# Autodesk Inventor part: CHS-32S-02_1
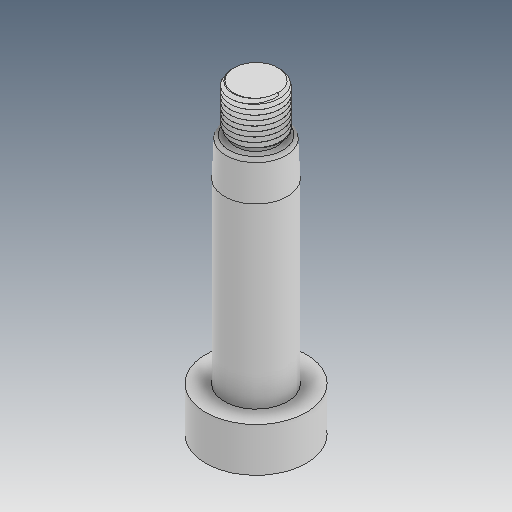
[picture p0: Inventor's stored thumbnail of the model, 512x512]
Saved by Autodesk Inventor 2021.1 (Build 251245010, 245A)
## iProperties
Created: 2019-04
Part Number: CHS-32S-02_1
Material: Ogólny
Document SubType Name: Modeling
Designer: user
Density: 1 g/cm^3
Appearance: Domyślna
Author: user
Revision Number: ÈÎºÎ
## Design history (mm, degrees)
feature "ÊäÈë1"
feature "ÊäÈë2"
node "Bryła1"
node "Bryła2"
